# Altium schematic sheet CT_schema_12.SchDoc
size 146 x 119 mm
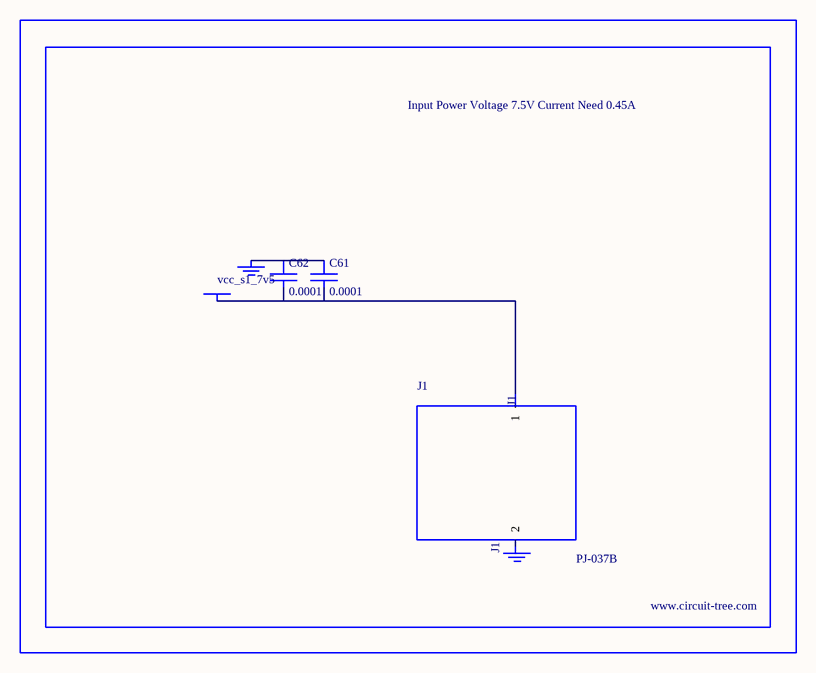
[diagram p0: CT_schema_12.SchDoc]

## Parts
BORDER11  (no value)
C61  0.0001  [EXV-9H]
C62  0.0001  [EXV-9H]
GND_INSTANCE_11_0  (no value)
GND_INSTANCE_11_1  (no value)
J1  PJ-037B  [PJ-037B_PACKAGE]
POWER_INSTANCE_11_0  vcc_s1_7v5

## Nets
NetC61_1: C61.1 C62.1 GND_INSTANCE_11_0.0(GND)
NetC61_2: C61.2 C62.2 J1.1 POWER_INSTANCE_11_0.0(PWR)

Not connected (* = marked no-connect by the designer): GND_INSTANCE_11_1 0(GND); J1 2

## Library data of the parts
BORDER11 = BORDER_PAGE11
C61 C62 = EDK107M035A9HAA
GND_INSTANCE_11_0 GND_INSTANCE_11_1 = GND
POWER_INSTANCE_11_0 = PWR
